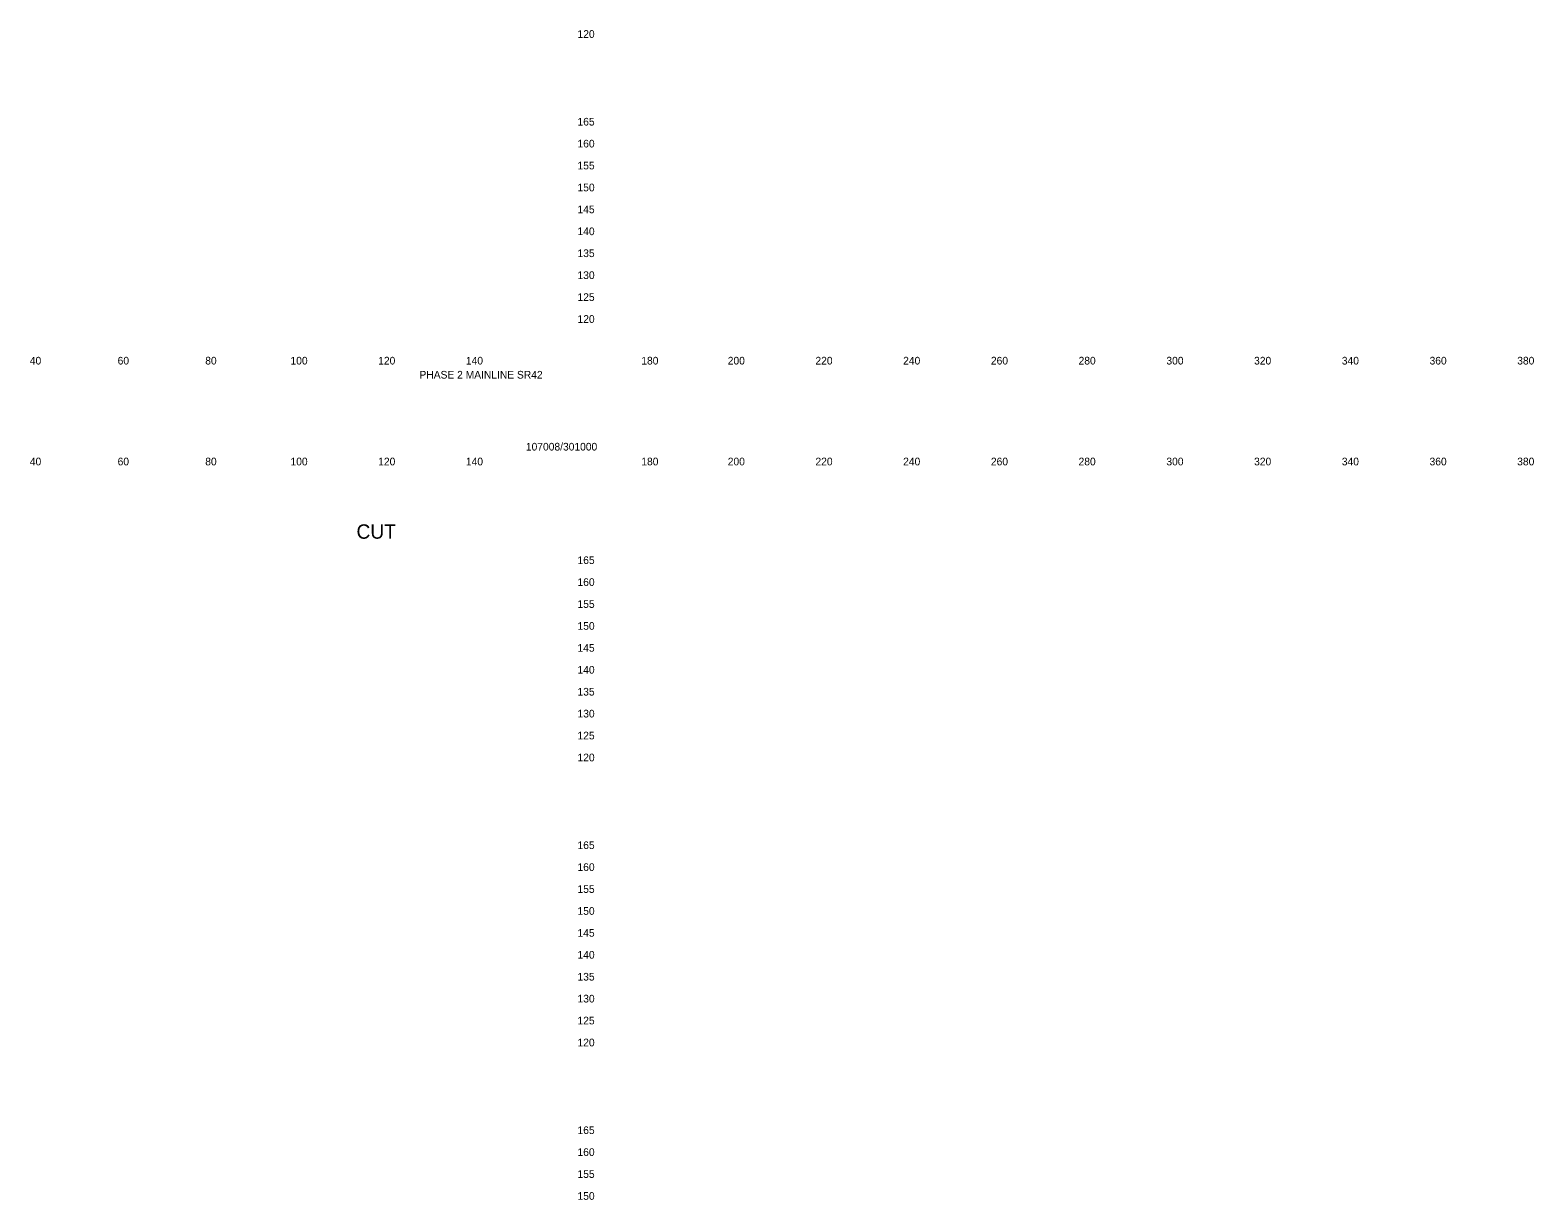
# Model space of a CAD drawing. Extents: x 21281 to 22024, y 6472 to 15208.
# Drawn here: x 21681.3 to 22024.2, y 6744.8 to 7011.6 of the extents above; entities that cross this region are included whole.
import ezdxf

# ---------------------------------------------------------------- set-up
doc = ezdxf.new("R2010")
doc.units = 0
doc.layers.add('XS_SHEET_LABELS_ELEVATION', color=7, linetype='Continuous')
doc.layers.add('XS_SHEET_LABELS_OFFSET', color=7, linetype='Continuous')

msp = doc.modelspace()

# ---------------------------------------------------------------- texts
at = {"layer": 'XS_SHEET_LABELS_ELEVATION'}
for s, p in [('  120  ', (21804.84, 7009.84)), ('  165  ', (21804.84, 6989.84)), ('  160  ', (21804.84, 6984.84)), ('  155  ', (21804.84, 6979.84)), ('  150  ', (21804.84, 6974.84)), ('  145  ', (21804.84, 6969.84)), ('  140  ', (21804.84, 6964.84)), ('  135  ', (21804.84, 6959.84)), ('  130  ', (21804.84, 6954.84)), ('  125  ', (21804.84, 6949.84)), ('  120  ', (21804.84, 6944.84)), ('  165  ', (21804.84, 6889.84)), ('  160  ', (21804.84, 6884.84)), ('  155  ', (21804.84, 6879.84)), ('  150  ', (21804.84, 6874.84)), ('  145  ', (21804.84, 6869.84)), ('  140  ', (21804.84, 6864.84)), ('  135  ', (21804.84, 6859.84)), ('  130  ', (21804.84, 6854.84)), ('  125  ', (21804.84, 6849.84)), ('  120  ', (21804.84, 6844.84)), ('  165  ', (21804.84, 6824.84)), ('  160  ', (21804.84, 6819.84)), ('  155  ', (21804.84, 6814.84)), ('  150  ', (21804.84, 6809.84)), ('  145  ', (21804.84, 6804.84)), ('  140  ', (21804.84, 6799.84)), ('  135  ', (21804.84, 6794.84)), ('  130  ', (21804.84, 6789.84)), ('  125  ', (21804.84, 6784.84)), ('  120  ', (21804.84, 6779.84)), ('  165  ', (21804.84, 6759.84)), ('  160  ', (21804.84, 6754.84)), ('  155  ', (21804.84, 6749.84)), ('  150  ', (21804.84, 6744.84))]:
    msp.add_text(s, height=1.75, dxfattribs=at).set_placement(p)
at = {"layer": 'XS_SHEET_LABELS_OFFSET'}
for s, height, p in [('  40  ', 1.75, (21679.95, 6935.34)), ('  60  ', 1.75, (21699.97, 6935.34)), ('  80  ', 1.75, (21719.95, 6935.34)), ('  100  ', 1.75, (21739.39, 6935.34)), ('  120  ', 1.75, (21759.39, 6935.34)), ('  140  ', 1.75, (21779.39, 6935.34)), ('  180  ', 1.75, (21819.39, 6935.34)), ('  200  ', 1.75, (21839.1, 6935.34)), ('  220  ', 1.75, (21859.1, 6935.34)), ('  240  ', 1.75, (21879.1, 6935.34)), ('  260  ', 1.75, (21899.11, 6935.34)), ('  280  ', 1.75, (21919.1, 6935.34)), ('  300  ', 1.75, (21939.13, 6935.34)), ('  320  ', 1.75, (21959.13, 6935.34)), ('  340  ', 1.75, (21979.13, 6935.34)), ('  360  ', 1.75, (21999.14, 6935.34)), ('  380  ', 1.75, (22019.13, 6935.34)), ('PHASE 2 MAINLINE SR42', 1.75, (21770.1, 6932.13)), ('107008/301000', 1.75, (21794.37, 6915.72)), ('  40  ', 1.75, (21679.95, 6912.34)), ('  60  ', 1.75, (21699.97, 6912.34)), ('  80  ', 1.75, (21719.95, 6912.34)), ('  100  ', 1.75, (21739.39, 6912.34)), ('  120  ', 1.75, (21759.39, 6912.34)), ('  140  ', 1.75, (21779.39, 6912.34)), ('  180  ', 1.75, (21819.39, 6912.34)), ('  200  ', 1.75, (21839.1, 6912.34)), ('  220  ', 1.75, (21859.1, 6912.34)), ('  240  ', 1.75, (21879.1, 6912.34)), ('  260  ', 1.75, (21899.11, 6912.34)), ('  280  ', 1.75, (21919.1, 6912.34)), ('  300  ', 1.75, (21939.13, 6912.34)), ('  320  ', 1.75, (21959.13, 6912.34)), ('  340  ', 1.75, (21979.13, 6912.34)), ('  360  ', 1.75, (21999.14, 6912.34)), ('  380  ', 1.75, (22019.13, 6912.34)), ('CUT', 3.273, (21755.74, 6895.61))]:
    msp.add_text(s, height=height, dxfattribs=at).set_placement(p)

doc.saveas('drawing.dxf')
